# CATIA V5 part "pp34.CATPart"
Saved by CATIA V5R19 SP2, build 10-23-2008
Part number: pp34
Bounding box of the stored display mesh (mm): x -15 to -10, y -270.121 to -217.75, z 24.561 to 52.25
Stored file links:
  C:\Users\Welcome\Documents\thinkm2\pp34.CATPart
  C:\Users\Welcome\Documents\thinkm2\Brasmeca.CATProduct
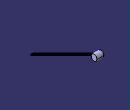
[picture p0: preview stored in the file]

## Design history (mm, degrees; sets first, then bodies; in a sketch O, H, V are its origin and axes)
AxisSystem1: origin (0, 0, 0), X (1, 0, 0), Y (0, 1, 0), Z (0, 0, 1)
Set1
  Plane1: linked copy from another document
  Line1: linked copy from another document
  Plane2: linked copy from another document
Body1 (main body)
  Sketch1 on Plane1, origin (-15, 0, 0), H (0, 1, 0), V (0, 0, 1)
    circle A1 centre (-220, 50) radius 2.25
    reference projected point E1 (-220, 50) from Line1
    radius A1 = 2.25
    distance A1 E1 = 2.25
  Pad1: profile Sketch1, direction (1, 0, 0), length 5
  Sketch2 on Plane2, origin (0, -206, -103), H (-1, 0, 0), V (0, -0.4472, 0.8944)
    line L1 (14.9507, 143.3798) -> (13.2847, 143.3798)
    line L2 (13.2847, 143.3798) -> (13.2847, 142.6178)
    line L3 (13.2847, 142.6178) -> (14.9507, 142.6178)
    line L4 (14.9507, 142.6178) -> (14.9507, 143.3798)
  Pad2: profile Sketch2, direction (0, 0.8944, 0.4472), length 57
